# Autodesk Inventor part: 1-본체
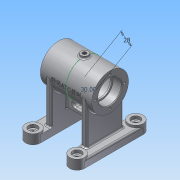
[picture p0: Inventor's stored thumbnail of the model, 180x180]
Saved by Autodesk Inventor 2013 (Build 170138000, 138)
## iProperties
Created: 2015-11
Part Number: 1-본체
Material: 알루미늄 6061
Document SubType Name: Modeling
Designer: user-11
Density: 2.71 g/cm^3
Mass: 357.662 g
Surface Area: 464.814 cm^2
Volume: 131.979 cm^3
Author: user-11
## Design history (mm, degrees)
sketch "스케치1"
  geometry: C1 r 25 at (0, 0); 1 further point
  constraints: 1 centre point, 1 coincident
  dimensions: "d0" = 50 diameter of C1
extrude "돌출1" new body sketch "스케치1" stored distance "d2" = 70; taper "d3" = 0 deg
sketch "스케치2"
  geometry: C1 r 25 at (0, 0) reference; C2 r 16 at (0, 0)
  constraints: 1 centre point, 1 coincident
  dimensions: "d4" = 32 diameter of C2
extrude "돌출2" cut sketch "스케치2" distance "d6" = 12; taper "d7" = 0 deg
sketch "스케치3"
  geometry: C1 r 16 at (0, 0) reference; C2 r 14 at (0, 0)
  constraints: 1 centre point, 1 coincident
  dimensions: "d8" = 28 diameter of C2
extrude "돌출3" cut sketch "스케치3" distance "d10" = 2; taper "d11" = 0 deg
sketch "스케치4"
  geometry: C1 r 14 at (0, 0) reference; C2 r 21 at (0, 0)
  constraints: 1 centre point, 1 coincident
  dimensions: "d12" = 42 diameter of C2
extrude "돌출4" cut sketch "스케치4" distance "d14" = 21; taper "d15" = 0 deg
sketch "스케치5"
  geometry: C1 r 16 at (0, 0) reference; 1 further point
  constraints: 1 vertical alignment
  dimensions: "d16" = 20 distance of C1.centre point (0, 20)
hole "구멍1" sketch "스케치5" at (0, 20) diameter "d17" = 3.242; stored, may be unused: countersink angle "d21" = 90 deg, drill point angle "d23" = 118 deg; dims "d18" = 8, "d19" = 4, "d20" = 2, "d22" = 10
node "작업 평면1"
sketch "스케치6"
  geometry: L1 (-50, -20)-(50, -20); L2 (50, -20)-(50, -40); L3 (50, -40)-(-50, -40); L4 (-50, -40)-(-50, -20); C1 r 10 at (-40, -30); C2 r 10 at (40, -30); 2 further points
  constraints: 8 end point, 6 tangent, 2 centre point, 2 parallel, 1 horizontal, 1 midpoint, 1 perpendicular, 1 vertical alignment
  dimensions: "d33" = 20 distance of L1.end L2.end; "d35" = 40 distance of point (0, -40) point (0, 0); "d36" = 80 distance of C2.centre C1.centre
extrude "돌출5" join sketch "스케치6" distance "d37" = 10; taper "d38" = 0 deg
fillet "모깎기1" dims "d39" = 10
sketch "스케치7"
  geometry: C1 r 10 at (-40, 30); C2 r 10 at (40, 30); A1 r 10 centre (40, 30) between (40, 20) and (40, 40) reference; A2 r 10 centre (-40, 30) between (-40, 40) and (-40, 20) reference; 1 further point
  constraints: 2 centre point, 2 coincident, 1 equal radius
  dimensions: "d40" = 20 diameter of C1
extrude "돌출6" join sketch "스케치7" distance "d42" = 3; taper "d43" = 0 deg
sketch "스케치8"
  geometry: C1 r 10 at (0, 0) reference; C2 r 10 at (-80, 0) reference; C3 r 6 at (-80, 0); C4 r 6 at (0, 0); 1 further point
  constraints: 2 centre point, 2 coincident, 1 equal radius
  dimensions: "d44" = 12 diameter of C3
extrude "돌출7" cut sketch "스케치8" distance "d46" = 4; taper "d47" = 0 deg
sketch "스케치9"
  geometry: C1 r 3 at (-40, -30); C2 r 3 at (40, -30); A1 r 10 centre (40, -30) between (40, -40) and (40, -20) reference; A2 r 10 centre (-40, -30) between (-40, -20) and (-40, -40) reference; 1 further point
  constraints: 2 centre point, 2 coincident, 1 equal radius
  dimensions: "d48" = 6 diameter of C1
extrude "돌출8" cut sketch "스케치9" distance "d50" = 8; taper "d51" = 0 deg
sketch "스케치10"
  geometry: C1 r 6 at (0, 0) reference; C2 r 6 at (-80, 0) reference; C3 r 3.5 at (-80, 0); C4 r 3.5 at (0, 0); 1 further point
  constraints: 2 centre point, 2 coincident, 1 equal radius
  dimensions: "d52" = 7 diameter of C3
extrude "돌출9" cut sketch "스케치10" distance "d54" = 1; taper "d55" = -45 deg
fillet "모깎기2" dims "d56" = 0.3
sketch "스케치11"
  geometry: L1 (-40, 20)-(40, 20) reference; L2 (-25, 20)-(-25, 28); L3 (-25, 28)-(25, 28); L4 (25, 28)-(25, 20); L5 (-40, -40)-(40, -40) reference; L6 (40, -20)-(-40, -20) reference; L7 (25, 20)-(4, 20); L8 (4, -20)-(25, -20); L9 (4, 20)-(4, -20); L10 (25, -20)-(25, -28); L11 (25, -28)-(-25, -28); L12 (-25, -28)-(-25, -20); L13 (-25, -20)-(-4, -20); L14 (-4, -20)-(-4, 20); L15 (-4, 20)-(-25, 20); C1 r 3 at (40, -30) reference; C2 r 3 at (-40, -30) reference; A1 r 10 centre (40, -30) between (40, -40) and (40, -20) reference; A2 r 10 centre (-40, -30) between (-40, -20) and (-40, -40) reference; 3 further points
  constraints: 24 end point, 8 point on line, 5 perpendicular, 4 vertical alignment, 3 parallel, 2 midpoint, 1 collinear
  dimensions: "d57" = 8 distance between parallel lines of L3 L15; "d59" = 8 distance between parallel lines of L13 L11; "d60" = 8 distance between parallel lines of L9 L14; "d61" = 4 distance from line of L14 point (0, 0); "d62" = 50 distance of L10.end L11.end
extrude "돌출10" join sketch "스케치11" stored distance "d63" = 1; taper "d64" = 0 deg
sketch "스케치12"
  geometry: L1 (40, 0)-(40, 33.322) reference; L2 (12, 26.5)-(28, 26.5); L3 (28, 19.5)-(12, 19.5); L4 (53, -10)-(47, -10) reference; A1 r 3.5 centre (28, 23) between (28, 19.5) and (28, 26.5); A2 r 3.5 centre (12, 23) between (12, 26.5) and (12, 19.5); 2 further points
  constraints: 4 end point, 4 point on circle, 4 tangent, 2 centre point, 1 midpoint, 1 parallel, 1 perpendicular, 1 vertical alignment
  dimensions: "d65" = 23 dimension on A1 A2; "d67" = 3.5 radius of A1; "d68" = 33 distance from line of A1.centre L4
extrude "돌출11" cut sketch "스케치12" distance "d69" = 8; taper "d70" = 0 deg
node "작업 평면2"
sketch "스케치14"
  geometry: L1 (-4, -20)-(-4, 20) reference; L2 (4, 20)-(4, -20) reference; L3 (-4, 20)-(4, 20); L4 (4, 20)-(4, -20); L5 (4, -20)-(-4, -20); L6 (-4, -20)-(-4, 20); 1 further point
  constraints: 8 end point, 2 parallel, 1 horizontal, 1 perpendicular
extrude "돌출12" cut sketch "스케치14" distance "d77" = 20; taper "d78" = 0 deg
node "작업 평면3"
sketch "스케치15"
  geometry: C1 r 5 at (0, 0); 1 further point
  constraints: 1 centre point, 1 coincident
  dimensions: "d80" = 10 diameter of C1
extrude "돌출13" join sketch "스케치15" stored distance "d82" = 20; taper "d83" = 0 deg
sketch "스케치16"
  geometry: C1 r 5 at (0, 0) reference; 1 further point
  constraints: 1 coincident
hole "구멍2" sketch "스케치16" at (0, 0) diameter "d84" = 5.188; stored, may be unused: countersink angle "d88" = 90 deg, drill point angle "d90" = 118 deg; dims "d85" = 8, "d86" = 4, "d87" = 2, "d89" = 15
node "작업 평면4"
sketch "스케치17"
  geometry: L1 (0, 0)-(14, -24.249); L2 (0, 0)-(0, -25)
  constraints: 4 end point, 1 vertical, 1 vertical alignment, 1 other
  dimensions: "d92" = 28 distance of L1.start L1.end; "d93" = 30 deg angle of L1 L2
node "작업 평면5"
sketch "스케치18"
  geometry: C1 r 6 at (0, 0); 1 further point
  constraints: 1 centre point, 1 coincident
  dimensions: "d94" = 12 diameter of C1
extrude "돌출14" join sketch "스케치18" stored distance "d96" = 20; taper "d97" = 0 deg
sketch "스케치19"
  geometry: C1 r 6 at (0, 0) reference; 1 further point
  constraints: 1 coincident
hole "구멍3" sketch "스케치19" at (0, 0) diameter "d98" = 5.188; stored, may be unused: countersink angle "d102" = 90 deg, drill point angle "d104" = 118 deg; dims "d99" = 8, "d100" = 4, "d101" = 2, "d103" = 15
node "작업 평면6"
sketch "스케치20"
  geometry: 2 further points
  constraints: 1 coincident, 1 other
feature "엠보싱1" sketch "스케치20" dims "d105" = 0.5, "d106" = 0
fillet "모깎기3" dims "d107" = 0.3
chamfer "모따기1" distance "d108" = 1; stored, may be unused: second distance "d109" = 2, angle "d110" = 45 deg
fillet "모깎기4" dims "d111" = 2
fillet "모깎기5" dims "d112" = 2
fillet "모깎기6" dims "d113" = 2
fillet "모깎기7" dims "d114" = 2
fillet "모깎기8" dims "d115" = 2
fillet "모깎기9" dims "d116" = 2
fillet "모깎기10" dims "d117" = 2
fillet "모깎기11" dims "d118" = 2
node "솔리드1"
mirror "대칭1"
pattern_circular "원형 패턴1" dims angle "d25" = 360 deg
mirror "대칭2"
mirror "대칭3"
node "투영된 루프1"
node "투영된 루프2"
other parameters: "d27" = -68, "d76" = -45, "d79" = 28, "d91" = 0
